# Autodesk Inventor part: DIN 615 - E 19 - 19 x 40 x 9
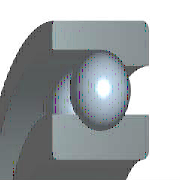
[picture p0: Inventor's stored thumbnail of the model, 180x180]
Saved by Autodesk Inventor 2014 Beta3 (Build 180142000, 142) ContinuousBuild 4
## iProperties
IsCustomPart: 0
Created: 2012-11
Part Number: DIN 615 - E 19 - 19 x 40 x 9
Material: Steel, Mild
Description: Magneto Ball Bearing
Document SubType Name: Modeling
Standard: DIN 615
Designer: Thomas
Standards Organization: DIN
Language: en-US
Size Designation: E 19 - 19 x 40 x 9
Categories: <MemberInstance><Categories><Category DisplayName="Shaft Parts" InternalName="7f7aeb1f-a693-4053-b835-cee3144e0d98" Mnemonic="SHFT"><Category DisplayName="Beari
Density: 1 g/cm^3
Appearance: Steel
Author: Thomas
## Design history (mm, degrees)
sketch "Sketch" dims "d4" = 6.09 (= DDB)
  geometry: L1 (1.455, 14.75)-(7.545, 14.75); L2 (2.064, 12.923)-(0, 12.923); L3 (6.936, 12.923)-(9, 12.923); L4 (4.5, 17.795)-(0, 17.795); L5 (0, 20)-(9, 20); L6 (0, 9.5)-(9, 9.5); L7 (9, 9.5)-(9, 12.923); L8 (6.936, 16.577)-(9, 16.577); L9 (9, 16.577)-(9, 20); L10 (4.5, 14.75)-(4.5, 17.795); L11 (4.5, 14.75)-(4.5, 11.705); L12 (-3.2, 0)-(19.2, 0) reference; L13 (0, -2.6)-(0, 17.35) reference
  constraints: 22 end point, 5 parallel, 4 collinear, 4 point on line, 2 perpendicular, 1 horizontal, 1 midpoint, 9 other
  dimensions: "d10" = 19 diameter of L6 L12 (= WD); "d12" = 33.154 diameter of L8 L12 (= KAD1); "d14" = 29.5 diameter of L10.start L12 (= DDA); "d15" = 40 diameter of L5 L12 (= BD); "d16" = 25.846 diameter of L2 L12 (= KID1); "d17" = 9 distance between parallel lines of L13 L7 (= KB); "d18" = 4.5 distance from line of L13 L10.start (= 0.5 x KB)
revolve "Body" stored, may be unused: angle "d8" = 90 deg
revolve "Ball" stored, may be unused: angle "d11" = 90 deg
pattern_circular "Balls" dims angle "d3" = 360 deg
body "Solid1"
fillet "Fillet1" dims "d0" = 0.6 (= KR1S), "d1" = 0.2 (= KR3S)
other parameters: "WD" = 19 [user parameter; used in 2 equation terms], "BD" = 40 [user parameter; used in 2 equation terms], "KB" = 9 [user parameter; used in 2 equation terms], "KR1S" = 0.6 [user parameter; used in 1 equation term], "KR3S" = 0.2 [user parameter; used in 1 equation term], "KID1" = 25.846 [user parameter; used in 1 equation term], "KAD1" = 33.154 [user parameter; used in 2 equation terms], "DDA" = 29.5 [user parameter; used in 1 equation term], "DDB" = 6.09 [user parameter; used in 2 equation terms], "d5" = 0, "d6" = 0, "d7" = 0, "d9" = 0, "d19" = 0, "WR" = 9.5 (= 0.5 x WD) [user parameter], "BC" = 8800000 [user parameter], "BC0" = 1570000 [user parameter], "DBB" = 35.59 [user parameter], "BBA" = 0 [user parameter]
